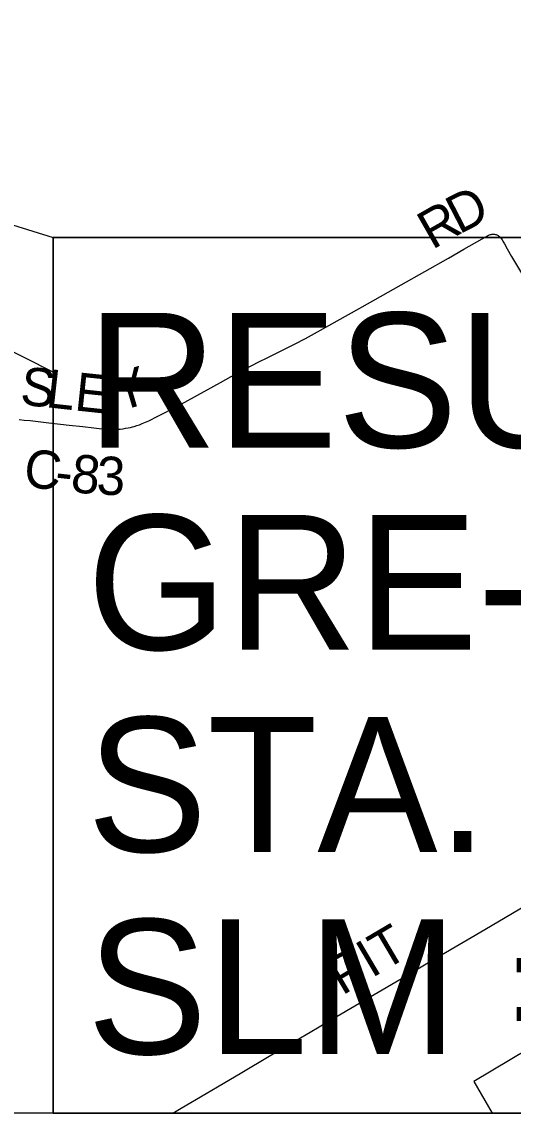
# Model space of a CAD drawing. Extents: x -19.5 to 44.1, y 0 to 22.
# Drawn here: x 6.7 to 7.429, y 17.897 to 19.517 of the extents above; entities that cross this region are included whole.
import ezdxf

# ---------------------------------------------------------------- set-up
doc = ezdxf.new("R2010")
doc.units = 0
for name, color, linetype in [('GM_X_County_Road', 7, 'Continuous'), ('GM_X_County_Road_Text', 7, 'Continuous'), ('GM_X_Township', 7, 'Continuous'), ('SH_Data', 7, 'Continuous'), ('SH_Masking', 7, 'Continuous'), ('SH_Text', 7, 'Continuous')]:
    doc.layers.add(name, color=color, linetype=linetype)

msp = doc.modelspace()

# ---------------------------------------------------------------- linework, layer by layer
at = {"layer": 'GM_X_County_Road'}
for points in [[(6.6964, 18.9266), (6.7038, 18.926), (6.7125, 18.9251), (6.7403, 18.9219), (6.7705, 18.9185), (6.7909, 18.9162), (6.8069, 18.9144), (6.823, 18.9127), (6.8275, 18.9124), (6.8329, 18.9122), (6.8376, 18.9122), (6.8423, 18.9123), (6.8463, 18.9126), (6.8509, 18.9131), (6.8543, 18.9137), (6.8583, 18.9144), (6.8615, 18.9151), (6.8643, 18.9158), (6.8672, 18.9166), (6.8709, 18.9177), (6.8747, 18.9191), (6.879, 18.9207), (6.8839, 18.9228), (6.8887, 18.9249), (6.9021, 18.9316), (6.9313, 18.9468), (6.9466, 18.955), (6.9951, 18.9816), (7.0189, 18.995), (7.0519, 19.0123), (7.0641, 19.0185), (7.1049, 19.0384), (7.1214, 19.0471), (7.1388, 19.0567), (7.2016, 19.092), (7.2633, 19.1268), (7.3331, 19.1662), (7.3563, 19.1794), (7.3833, 19.1948), (7.3887, 19.198), (7.3914, 19.1994), (7.3929, 19.2002), (7.3943, 19.2008), (7.3954, 19.2013), (7.3964, 19.2016), (7.3976, 19.2019), (7.3991, 19.202), (7.4002, 19.202), (7.4015, 19.2019), (7.403, 19.2016), (7.404, 19.2013), (7.405, 19.2009), (7.4062, 19.2003), (7.407, 19.1998), (7.4076, 19.1993), (7.4088, 19.1983), (7.4098, 19.1972), (7.4107, 19.1962), (7.4118, 19.1948), (7.4128, 19.1934), (7.4139, 19.1917), (7.4163, 19.1875), (7.4204, 19.1803), (7.4268, 19.1689), (7.4429, 19.1416)], [(6.9241, 17.8973), (6.9369, 17.9049), (6.9738, 17.9266), (6.9904, 17.9364), (7.0268, 17.9578), (7.0674, 17.982), (7.128, 18.0175), (7.1681, 18.0412), (7.2147, 18.0686), (7.2694, 18.1006), (7.3111, 18.1253), (7.3609, 18.1545), (7.3873, 18.1699), (7.4284, 18.1943), (7.4825, 18.2261)]]:
    msp.add_lwpolyline(points, dxfattribs=at)
at = {"layer": 'GM_X_Township'}
msp.add_lwpolyline([(9.4, 19.1723), (8.6813, 18.7543), (8.2198, 18.4859), (7.9056, 18.293), (7.7378, 18.1897), (7.7481, 18.1694), (7.371, 17.9444), (7.3983, 17.8973)], dxfattribs=at)
at = {"layer": 'SH_Data'}
msp.add_line((9.4, 17.8973), (2.6, 17.8973), dxfattribs=at)
at = {"layer": 'SH_Masking'}
msp.add_lwpolyline([(6.7466, 19.1971), (9.4, 19.1971), (9.4, 17.8973), (6.7466, 17.8973)], close=True, dxfattribs=at)
at = {"layer": 'SH_Text'}
for points in [[(6.7466, 18.9971), (5.7192, 19.517), (6.7466, 19.1971)], [(6.7466, 17.8973), (9.4, 17.8973), (9.4, 19.1971), (6.7466, 19.1971)]]:
    msp.add_lwpolyline(points, close=True, dxfattribs=at)

# ---------------------------------------------------------------- texts
at = {"layer": 'GM_X_County_Road_Text'}
for s, height, rotation, p in [('D', 0.0568, 27.2884, (7.3491, 19.201)), ('R', 0.0568, 29.6577, (7.3091, 19.1782)), ('S', 0.0568, 354.1646, (6.6965, 18.9491)), ('L', 0.0568, 353.6186, (6.7345, 18.9453)), ('Y', 0.0568, 16.4437, (6.8435, 18.9382)), ('E', 0.0568, 353.9618, (6.7771, 18.9405)), ('C', 0.0568, 353.4995, (6.7014, 18.8274)), ('8', 0.0568, 354.0388, (6.7715, 18.8195)), ('3', 0.0568, 357.9213, (6.8105, 18.8156)), ('-', 0.0568, 353.6144, (6.7479, 18.8221)), ('PIT', 0.05682, 30.5278, (7.1755, 18.0714))]:
    msp.add_text(s, height=height, rotation=rotation, dxfattribs=at).set_placement(p)
at = {"layer": 'SH_Text'}
for s, p in [('RESUME PROJECT', (6.797, 18.8851)), ('GRE-42-2021', (6.797, 18.5851)), ('STA. 106+63.19', (6.797, 18.2851)), ('SLM = 20.29', (6.797, 17.9851))]:
    msp.add_text(s, height=0.2, rotation=360, dxfattribs=at).set_placement(p)

doc.saveas('drawing.dxf')
